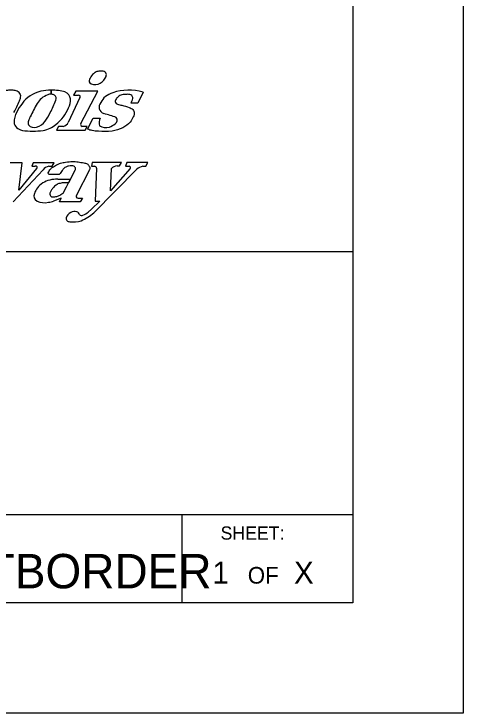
# Model space of a CAD drawing. Extents: x -0.22 to 2.83, y -0.07 to 1.83.
# Drawn here: x 2.6636 to 2.8333, y 0 to 0.2643 of the extents above; entities that cross this region are included whole.
import ezdxf

# ---------------------------------------------------------------- set-up
doc = ezdxf.new("R2010")
doc.units = 0
for name, color, linetype in [('SH_General_Details', 7, 'Continuous'), ('SH_General_Details_Sheet_Number-ILTollway', 7, 'Continuous'), ('SH_General_Details_Sheet_Standard-ILTollway', 7, 'Continuous'), ('SH_General_Details_Total_Sheet_Number-ILTollway', 7, 'Continuous'), ('SH_Printer Plotting Border-ILTollway', 7, 'Continuous')]:
    doc.layers.add(name, color=color, linetype=linetype)

msp = doc.modelspace()

# ---------------------------------------------------------------- linework, layer by layer
at = {"layer": 'SH_General_Details'}
for p, q in [((2.677722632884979, 0.23550538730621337), (2.677722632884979, 0.23398690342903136)), ((2.677722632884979, 0.23398690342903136), (2.677722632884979, 0.23550538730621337)), ((2.6885865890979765, 0.2327443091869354), (2.68415580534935, 0.22329691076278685)), ((2.712401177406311, 0.23480902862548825), (2.7104256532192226, 0.2306287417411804)), ((2.7104256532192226, 0.2306287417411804), (2.707885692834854, 0.2306287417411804)), ((2.691431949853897, 0.2207216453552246), (2.693539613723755, 0.22497970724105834)), ((2.693539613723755, 0.22497970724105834), (2.696267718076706, 0.22497970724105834)), ((2.6804911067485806, 0.22181505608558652), (2.679698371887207, 0.22034836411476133)), ((2.679698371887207, 0.22034836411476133), (2.690483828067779, 0.22034499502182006)), ((2.682211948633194, 0.22181223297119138), (2.6804911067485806, 0.22181505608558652)), ((2.6912765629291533, 0.22181168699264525), (2.689411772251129, 0.22182814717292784)), ((2.690483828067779, 0.22034499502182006), (2.6912765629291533, 0.22181168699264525)), ((2.6914229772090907, 0.2207241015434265), (2.691431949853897, 0.2207216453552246)), ((2.6666739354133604, 0.2080908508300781), (2.6621581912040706, 0.2080908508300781)), ((2.663346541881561, 0.19334409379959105), (2.6746359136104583, 0.20542692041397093)), ((2.6807524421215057, 0.20365352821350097), (2.6769743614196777, 0.20365352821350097)), ((2.6850233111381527, 0.20185651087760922), (2.6867754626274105, 0.20527522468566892)), ((2.6921414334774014, 0.20540671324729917), (2.6872682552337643, 0.19580801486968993)), ((2.693792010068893, 0.1891406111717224), (2.710100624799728, 0.20560188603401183)), ((2.6948400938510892, 0.2060494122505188), (2.694351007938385, 0.19350281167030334)), ((2.680150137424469, 0.20185651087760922), (2.6850233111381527, 0.20185651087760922)), ((2.6850233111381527, 0.20185651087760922), (2.684256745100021, 0.20049779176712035)), ((2.684256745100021, 0.20049779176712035), (2.6850233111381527, 0.20185651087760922)), ((2.7916666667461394, 0.17433751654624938), (2.4316674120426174, 0.17433751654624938)), ((2.7916666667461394, 0.07499986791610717), (2.4316674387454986, 0.07499986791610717)), ((2.727257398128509, 0.04166674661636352), (2.7272573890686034, 0.07499992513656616))]:
    msp.add_line(p, q, dxfattribs=at)
msp.add_lwpolyline([(0.1666666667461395, 0.0416666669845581), (0.1666666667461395, 1.791666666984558), (2.7916666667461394, 1.791666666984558), (2.7916666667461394, 0.0416666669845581)], close=True, dxfattribs=at)
for points in [[(2.6869759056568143, 0.2350827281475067), (2.68618249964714, 0.23364955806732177)], [(2.68618249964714, 0.23364955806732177), (2.688017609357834, 0.23364955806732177)], [(2.6889164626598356, 0.22286735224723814), (2.695271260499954, 0.23508543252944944), (2.6869759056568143, 0.2350827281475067)], [(2.672199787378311, 0.20590262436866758), (2.6654261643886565, 0.19772055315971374), (2.6666739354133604, 0.2080908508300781)], [(2.67089259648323, 0.2080908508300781), (2.6703578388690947, 0.20680645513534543), (2.6716650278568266, 0.20680645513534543)], [(2.6767749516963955, 0.20680645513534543), (2.6780821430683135, 0.20680645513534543), (2.6788545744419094, 0.2080908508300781), (2.67089259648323, 0.2080908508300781)], [(2.7026660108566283, 0.2068549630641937), (2.7035604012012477, 0.2068549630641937), (2.7042311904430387, 0.20810803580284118), (2.693219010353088, 0.20810803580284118), (2.6929395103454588, 0.20681020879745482), (2.6940575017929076, 0.20681020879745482)], [(2.7123366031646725, 0.20676545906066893), (2.7134545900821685, 0.20676545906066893), (2.71423718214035, 0.20810803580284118), (2.706243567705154, 0.20810803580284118), (2.705740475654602, 0.20681020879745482), (2.7071379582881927, 0.20681020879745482)], [(2.70752925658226, 0.20587040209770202), (2.7000946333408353, 0.19750165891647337), (2.7004859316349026, 0.20587040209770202)], [(2.684256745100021, 0.20049779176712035), (2.681792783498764, 0.20049779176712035)], [(2.682176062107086, 0.1965969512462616), (2.6835449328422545, 0.19896375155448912), (2.684256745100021, 0.20049779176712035)], [(2.687852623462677, 0.1947122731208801), (2.689513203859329, 0.1947122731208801), (2.6886918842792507, 0.19326589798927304), (2.6808071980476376, 0.19326589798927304), (2.6814642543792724, 0.1947122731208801), (2.6786170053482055, 0.19352887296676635)], [(2.694351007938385, 0.19350281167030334), (2.6961118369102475, 0.19350281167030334), (2.692953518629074, 0.19048282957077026), (2.691723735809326, 0.18940905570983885)]]:
    msp.add_lwpolyline(points, dxfattribs=at)
for centre, major_axis, ratio, start_param, end_param in [((2.6999652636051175, 0.2375553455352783), (-0.008237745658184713, 1.0088328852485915e-18), 0.8000752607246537, 5.657384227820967, 5.961923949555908), ((2.692348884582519, 0.24230186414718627), (0.006436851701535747, -1.5765739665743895e-18), 0.8000752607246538, 5.35994097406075, 5.975474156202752), ((2.6938173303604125, 0.2390981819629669), (-0.00179891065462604, 2.2030301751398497e-19), 0.8000752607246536, 5.899852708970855, 7.2592592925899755), ((2.694211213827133, 0.24040055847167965), (-0.003418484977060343, 4.1864366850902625e-19), 0.800075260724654, 1.1482793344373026, 2.20319774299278), ((2.6778777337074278, 0.2225923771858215), (-0.016140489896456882, 1.9766399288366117e-18), 0.8000752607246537, 4.721998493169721, 4.969094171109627), ((2.6778777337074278, 0.2225923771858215), (-0.016140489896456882, 1.9766399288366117e-18), 0.8000383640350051, 4.395078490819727, 4.7149049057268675), ((2.7071054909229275, 0.22304212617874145), (0.01563161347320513, -3.82864108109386e-18), 0.8000752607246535, 1.2251758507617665, 1.9740563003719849), ((2.677345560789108, 0.22580751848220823), (-0.012129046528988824, 1.4853798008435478e-18), 0.8000752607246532, 5.01078761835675, 5.765691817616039), ((2.6803047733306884, 0.22758793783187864), (-0.008689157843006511, 1.0641149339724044e-18), 0.8000752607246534, 5.175654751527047, 5.860096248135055), ((2.6774772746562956, 0.2320206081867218), (-0.0024698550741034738, 3.024700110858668e-19), 0.8000752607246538, 4.612883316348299, 5.153926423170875), ((2.6774772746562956, 0.2320206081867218), (-0.0024698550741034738, 3.024700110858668e-19), 0.8000752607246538, 4.071840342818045, 4.566171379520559), ((2.6774212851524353, 0.23236350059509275), (0.002180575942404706, -5.340870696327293e-19), 0.8000752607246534, 5.909204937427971, 7.074943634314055), ((2.6809203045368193, 0.23198325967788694), (0.004112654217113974, -1.0073097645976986e-18), 0.8000752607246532, 0.08712246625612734, 1.0647598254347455), ((2.687906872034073, 0.23303792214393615), (0.0007724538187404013, -1.8919661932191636e-19), 0.800075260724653, 5.788124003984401, 7.71013160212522), ((2.703739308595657, 0.22878499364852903), (-0.007713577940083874, 9.44640853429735e-19), 0.8000752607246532, 5.0794162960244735, 5.947658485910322), ((2.6937143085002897, 0.2178005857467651), (-0.03131109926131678, 3.8345037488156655e-18), 0.8000752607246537, 5.7465390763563, 5.900046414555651), ((2.7748348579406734, 0.19390384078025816), (-0.11217070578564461, 1.3736949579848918e-17), 0.8000752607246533, 5.863868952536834, 5.924634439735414), ((2.62606113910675, 0.24434618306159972), (0.0556713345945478, -1.3635544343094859e-17), 0.8000752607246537, 5.883899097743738, 5.995916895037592), ((2.672557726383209, 0.2323223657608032), (0.012459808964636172, -3.051773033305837e-18), 0.8000752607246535, 5.922241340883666, 6.277888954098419), ((2.699367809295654, 0.22914537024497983), (-0.0035839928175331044, 4.389125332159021e-19), 0.8000752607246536, 5.6607938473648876, 7.348319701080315), ((2.665271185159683, 0.233605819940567), (0.019872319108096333, -4.867314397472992e-18), 0.8000752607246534, 5.5091350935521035, 5.976236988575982), ((2.674661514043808, 0.22350584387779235), (-0.01098572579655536, 1.3453633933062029e-18), 0.8000752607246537, 5.853724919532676, 6.297771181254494), ((2.6506869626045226, 0.2350934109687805), (0.028507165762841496, -6.98224186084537e-18), 0.8000752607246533, 5.76243947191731, 5.92185011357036), ((2.7011339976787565, 0.22313573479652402), (-0.005384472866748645, 6.5940774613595e-19), 0.8000752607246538, 5.840866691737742, 6.548879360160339), ((2.6885973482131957, 0.20284208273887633), (0.03108248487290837, -7.613013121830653e-18), 0.8000752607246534, 1.1146700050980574, 1.2758801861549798), ((2.7003394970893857, 0.2242215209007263), (0.0022798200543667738, -5.583948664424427e-19), 0.8000752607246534, 5.41802630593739, 6.828748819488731), ((2.667664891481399, 0.22343681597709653), (-0.0039886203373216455, 4.88465112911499e-19), 0.8000752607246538, 0.018542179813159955, 1.3534190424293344), ((2.6713157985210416, 0.22325227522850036), (-0.002357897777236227, 2.887591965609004e-19), 0.8000752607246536, 0.5153538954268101, 1.9459629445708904), ((2.6701127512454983, 0.22601519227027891), (0.006013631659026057, -1.4729149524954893e-18), 0.8000752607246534, 5.063271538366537, 5.7920136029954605), ((2.672220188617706, 0.22813850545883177), (0.010126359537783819, -2.480242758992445e-18), 0.8000752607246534, 4.9562759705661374, 5.511991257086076), ((2.6813631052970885, 0.22408055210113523), (0.0029594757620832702, -7.2486250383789e-19), 0.8000752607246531, 5.003296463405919, 5.945866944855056), ((2.6897492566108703, 0.22252627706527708), (-0.0009355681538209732, 1.1457405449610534e-19), 0.8000752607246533, 5.810064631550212, 7.484931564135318), ((2.6973413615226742, 0.22593837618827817), (0.005924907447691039, -1.4511837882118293e-18), 0.8000752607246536, 5.122073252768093, 5.568902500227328), ((2.6708979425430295, 0.23879757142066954), (0.023453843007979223, -5.744534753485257e-18), 0.8000752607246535, 4.536965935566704, 4.873723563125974), ((2.698293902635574, 0.22455339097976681), (0.003961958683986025, -9.704000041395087e-19), 0.800075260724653, 4.075728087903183, 5.075565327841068), ((2.6718014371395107, 0.20630493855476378), (-0.0006415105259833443, 7.856238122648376e-20), 0.8000752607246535, 2.240755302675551, 4.926665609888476), ((2.6786161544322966, 0.20322768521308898), (-0.004837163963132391, 5.923817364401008e-19), 0.8000752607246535, 5.102873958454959, 5.678790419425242), ((2.6938554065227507, 0.20603908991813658), (0.0009847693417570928, -2.411989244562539e-19), 0.8000752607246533, 0.013105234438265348, 1.364108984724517), ((2.702730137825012, 0.2047267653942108), (-0.002660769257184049, 3.2585025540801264e-19), 0.8000752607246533, 4.736493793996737, 5.716049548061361), ((2.706971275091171, 0.20624373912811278), (0.0007273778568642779, -1.7815619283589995e-19), 0.8000752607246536, 5.58671279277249, 7.622770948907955), ((2.7134031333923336, 0.20349651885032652), (-0.00422269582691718, 5.171310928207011e-19), 0.800075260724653, 4.967725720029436, 5.610393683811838), ((2.6798079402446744, 0.19477745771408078), (0.00885459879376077, -2.168751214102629e-18), 0.8000752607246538, 1.532140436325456, 2.2138077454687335), ((2.681011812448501, 0.19436913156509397), (-0.010006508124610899, 1.2254438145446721e-18), 0.8000752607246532, 5.421148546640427, 6.024304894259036), ((2.674052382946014, 0.19551704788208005), (-0.0029383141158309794, 3.598396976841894e-19), 0.8000752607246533, 5.889585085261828, 7.258805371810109), ((2.687964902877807, 0.1953982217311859), (-0.000864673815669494, 1.0589200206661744e-19), 0.8000752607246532, 5.649203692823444, 7.723758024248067), ((2.675246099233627, 0.1975628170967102), (-0.005742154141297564, 7.032110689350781e-19), 0.8000752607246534, 1.0532160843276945, 1.8172744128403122), ((2.675063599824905, 0.20100443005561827), (0.009996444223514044, -2.4484226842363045e-18), 0.8000752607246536, 4.871468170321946, 5.075802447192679), ((2.687607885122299, 0.1864386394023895), (-0.004317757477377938, 5.287727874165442e-19), 0.8000752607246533, 5.308575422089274, 6.062627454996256), ((2.686509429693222, 0.18802140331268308), (0.002073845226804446, -5.079455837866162e-19), 0.8000752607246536, 1.1610346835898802, 2.2644571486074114), ((2.686640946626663, 0.18820606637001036), (0.001809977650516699, -4.4331666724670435e-19), 0.8000752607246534, 0.1672490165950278, 1.176879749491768), ((2.6892302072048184, 0.18900743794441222), (0.0010666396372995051, -2.612513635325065e-19), 0.8000752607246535, 3.8578413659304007, 5.180372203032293), ((2.6802619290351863, 0.19916098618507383), (0.018436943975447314, -4.515748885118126e-18), 0.8000752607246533, 5.2052083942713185, 5.536371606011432), ((2.685642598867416, 0.19444732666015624), (0.008754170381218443, -2.1441533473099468e-18), 0.8000752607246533, 5.195774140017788, 5.480330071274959), ((2.684836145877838, 0.18694080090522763), (-0.0014758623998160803, 1.807410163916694e-19), 0.8000752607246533, 6.066729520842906, 7.786283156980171), ((2.6860296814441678, 0.19157500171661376), (-0.007378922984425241, 9.036574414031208e-19), 0.8000752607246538, 1.3946067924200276, 1.9828177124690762)]:
    msp.add_ellipse(centre, major_axis=major_axis, ratio=ratio, start_param=start_param, end_param=end_param, dxfattribs=at)
for points in [[(2.6984833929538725, 0.24074205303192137), (2.698543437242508, 0.24139097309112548), (2.698333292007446, 0.24203988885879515), (2.697732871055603, 0.2426167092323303), (2.6968322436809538, 0.2427609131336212), (2.695361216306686, 0.24264074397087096), (2.6940102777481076, 0.2420158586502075), (2.6932886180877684, 0.24141589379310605)], [(2.6636318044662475, 0.22710824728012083), (2.665756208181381, 0.2314826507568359), (2.6661532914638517, 0.23283391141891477), (2.6660341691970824, 0.23399440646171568), (2.665835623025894, 0.23431235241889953), (2.665279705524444, 0.23483696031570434), (2.664465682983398, 0.23528208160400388), (2.662897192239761, 0.23552054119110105), (2.66228171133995, 0.2355682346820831), (2.6615669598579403, 0.23550464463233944), (2.660038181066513, 0.23528208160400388), (2.657933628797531, 0.23466209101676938), (2.6565209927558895, 0.23410625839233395), (2.6549143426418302, 0.233294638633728)], [(2.707885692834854, 0.2306287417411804), (2.7082149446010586, 0.23138194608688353), (2.708497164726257, 0.23232345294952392), (2.7083560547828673, 0.2332272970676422), (2.7077916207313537, 0.23375454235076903), (2.706239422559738, 0.23394284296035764), (2.7044050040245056, 0.23375454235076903), (2.7029939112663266, 0.2330013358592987), (2.7021472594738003, 0.23202217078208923), (2.702006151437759, 0.23081704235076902), (2.702711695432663, 0.23025214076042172), (2.7044520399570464, 0.2298002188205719), (2.7071801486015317, 0.2289340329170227), (2.7085442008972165, 0.22818082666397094), (2.709108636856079, 0.226825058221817), (2.708732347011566, 0.22543162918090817), (2.707556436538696, 0.22347329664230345), (2.7047812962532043, 0.22128900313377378), (2.700689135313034, 0.22004621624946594), (2.695562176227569, 0.21997089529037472), (2.693210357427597, 0.22023451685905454), (2.6914229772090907, 0.2207241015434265)], [(2.6692641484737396, 0.22232252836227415), (2.669176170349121, 0.22257139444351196), (2.669161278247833, 0.22368050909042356), (2.6694293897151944, 0.22437221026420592), (2.6697974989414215, 0.22539694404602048)], [(2.6769743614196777, 0.20365352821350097), (2.676643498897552, 0.20388088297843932), (2.6767944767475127, 0.20468631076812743), (2.677675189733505, 0.2059145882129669), (2.678555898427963, 0.2065790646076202), (2.6800405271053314, 0.2074448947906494), (2.6811980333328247, 0.2078878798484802), (2.6831607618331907, 0.20827045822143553), (2.6857274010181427, 0.20855235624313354), (2.6868094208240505, 0.20851208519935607), (2.6889231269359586, 0.20823018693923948), (2.690055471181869, 0.20802882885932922), (2.6913136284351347, 0.20764625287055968), (2.691665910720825, 0.20732408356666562), (2.6919427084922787, 0.20692136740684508), (2.692244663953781, 0.2062971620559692), (2.6921414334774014, 0.20540671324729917)], [(2.6867754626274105, 0.20527522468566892), (2.68691007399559, 0.20575349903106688), (2.6866836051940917, 0.20641797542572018), (2.6862306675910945, 0.2068005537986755), (2.685450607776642, 0.20696164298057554), (2.6842931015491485, 0.20682068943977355), (2.683236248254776, 0.20645824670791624), (2.682607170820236, 0.20601526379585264), (2.681902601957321, 0.2051695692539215), (2.6807524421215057, 0.20365352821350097)], [(2.681792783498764, 0.20049779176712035), (2.681041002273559, 0.20027854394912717), (2.6802609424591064, 0.20005705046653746), (2.6795815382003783, 0.19965433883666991), (2.678449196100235, 0.1986072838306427), (2.6776691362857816, 0.197519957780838), (2.677241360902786, 0.19663399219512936), (2.677316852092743, 0.19578829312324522), (2.67751815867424, 0.19538557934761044), (2.678751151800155, 0.19518422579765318), (2.680135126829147, 0.1954258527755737), (2.681368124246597, 0.19602992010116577), (2.682176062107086, 0.1965969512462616)]]:
    msp.add_spline(points, degree=3, dxfattribs=at)
at = {"layer": 'SH_Printer Plotting Border-ILTollway'}
msp.add_lwpolyline([(0, 1.833282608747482), (2.833327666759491, 1.833282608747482), (2.833327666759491, 0), (0, 0)], close=True, dxfattribs=at)

# ---------------------------------------------------------------- texts
at = {"layer": 'SH_General_Details'}
for s, height, p in [('SHEET:', 0.004999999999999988, (2.7417119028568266, 0.06555551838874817)), ('OF', 0.0062999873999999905, (2.751983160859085, 0.04893333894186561))]:
    msp.add_text(s, height=height, rotation=1.0784289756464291e-05, dxfattribs=at).set_placement(p)
at = {"layer": 'SH_General_Details_Sheet_Number-ILTollway'}
msp.add_text('1', height=0.008333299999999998, rotation=1.0784289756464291e-05, dxfattribs=at).set_placement((2.738644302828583, 0.04893335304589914))
at = {"layer": 'SH_General_Details_Sheet_Standard-ILTollway'}
msp.add_text('STANDARDSHEETBORDER', height=0.013, dxfattribs=at).set_placement((2.510364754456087, 0.047145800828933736))
at = {"layer": 'SH_General_Details_Total_Sheet_Number-ILTollway'}
msp.add_text('X', height=0.008333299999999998, rotation=1.0784289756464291e-05, dxfattribs=at).set_placement((2.769456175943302, 0.048933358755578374))

doc.saveas('drawing.dxf')
